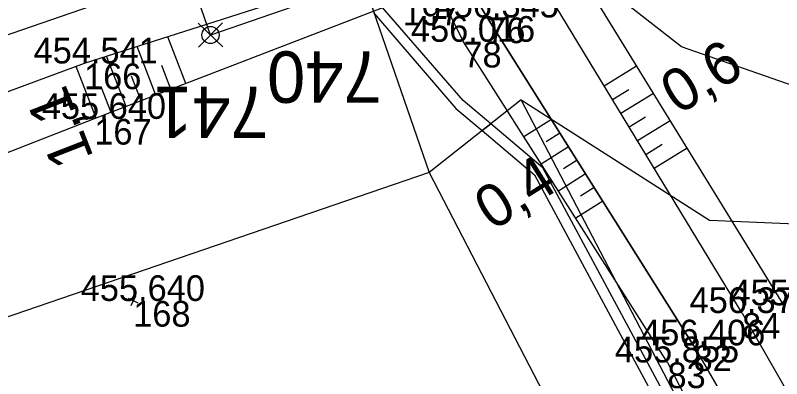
# Model space of a CAD drawing. Extents: x -776734 to -748832, y -1118122 to -976986.
# Drawn here: x -750922.61 to -750886.83, y -1114636.27 to -1114619.29 of the extents above; entities that cross this region are included whole.
import ezdxf

# ---------------------------------------------------------------- set-up
doc = ezdxf.new("R2010")
doc.units = 0
for name, color, linetype in [('KM_Hranice parcel', 7, 'Continuous'), ('KM_Věcná břemena k části', 7, 'Continuous'), ('Obvod stavby - SŽ+ČD', 7, 'Continuous'), ('SŽG Vrstva 48', 7, 'Continuous'), ('SŽG Vrstva 49', 7, 'Continuous'), ('SŽG Vrstva 51', 7, 'Continuous'), ('SŽG Vrstva 53', 7, 'Continuous'), ('SŽG Vrstva 60', 7, 'Continuous'), ('SŽG Vrstva 61', 7, 'Continuous'), ('VYT-BODY', 7, 'Continuous')]:
    doc.layers.add(name, color=color, linetype=linetype)

msp = doc.modelspace()

# ---------------------------------------------------------------- linework, layer by layer
at = {"layer": 'KM_Hranice parcel'}
msp.add_line((-750898.99, -1114623.24), (-750903.28, -1114626.63), dxfattribs=at)
for points in [[(-750899.97, -1114614.15), (-750906.35, -1114617.75), (-750903.28, -1114626.63)], [(-750898.99, -1114623.24), (-750890.19, -1114628.86), (-750790.97, -1114633.08), (-750787.69, -1114636.32), (-750785.63, -1114639.42), (-750784.78, -1114643.94), (-750782.09, -1114625.64), (-750786.55, -1114630.1), (-750878.13, -1114625.43), (-750891.51, -1114620.76), (-750899.97, -1114614.15)], [(-750670.16, -1114976.1), (-750672.09, -1114956.8), (-750700.84, -1114952.52), (-750709.51, -1114952.05), (-750748.78, -1114936.22), (-750768.56, -1114928.51), (-750782.18, -1114919.09), (-750798.79, -1114874.71), (-750803.56, -1114853.05), (-750810, -1114798.7), (-750817.87, -1114778.74), (-750898.99, -1114623.24)], [(-750903.28, -1114626.63), (-750977.55, -1114652.09), (-751017.8, -1114665.47), (-751047.63, -1114693.52)], [(-750903.28, -1114626.63), (-750826.19, -1114775.52), (-750817.2, -1114796.72), (-750809.54, -1114845.73), (-750803.72, -1114890), (-750794.3, -1114916.76)]]:
    msp.add_lwpolyline(points, dxfattribs=at)
at = {"layer": 'KM_Věcná břemena k části'}
msp.add_lwpolyline([(-750902.04, -1114623.64), (-750900.81, -1114624.68), (-750900.41, -1114624.36), (-750901.69, -1114623.28), (-750906.28, -1114617.96), (-750905.84, -1114619.22)], close=True, dxfattribs=at)
msp.add_lwpolyline([(-750864.07, -1114688.15), (-750867.37, -1114681.99), (-750869.16, -1114678.88), (-750873.3, -1114672.49), (-750878.91, -1114662.72), (-750880.52, -1114659.87), (-750884.7, -1114651.27), (-750887.27, -1114646.41), (-750887.94, -1114645.1), (-750897.97, -1114626.42), (-750900.41, -1114624.36), (-750900.81, -1114624.68), (-750898.37, -1114626.74), (-750888.38, -1114645.33), (-750887.67, -1114646.72), (-750885.15, -1114651.49), (-750880.97, -1114660.09), (-750879.19, -1114663.23), (-750873.73, -1114672.72), (-750870.82, -1114677.24), (-750869.61, -1114679.12), (-750867.78, -1114682.28), (-750864.58, -1114688.26)], dxfattribs=at)
at = {"layer": 'Obvod stavby - SŽ+ČD'}
msp.add_lwpolyline([(-751001.9301, -1114630.5149), (-750919.7259, -1114602.1536), (-750923.65, -1114590.78), (-750909.46, -1114590.94), (-750904.52, -1114591.74), (-750900.07, -1114579.45), (-750884.93, -1114572.87), (-750860.41, -1114581.47), (-750855.8233, -1114579.7245), (-750849.5295, -1114597.9668), (-750894.76, -1114611.21), (-750899.97, -1114614.15), (-750906.35, -1114617.75), (-750913.4946, -1114620.2148), (-750914.5076, -1114617.2787), (-750996.7117, -1114645.64)], dxfattribs=at)
at = {"layer": 'SŽG Vrstva 48'}
for p, q in [((-750914.639, -1114622.476), (-750915.483, -1114620.292)), ((-750916.038, -1114623.017), (-750916.914, -1114620.75)), ((-750917.437, -1114623.558), (-750918.346, -1114621.208)), ((-750918.836, -1114624.099), (-750919.77, -1114621.682)), ((-750915.338, -1114622.746), (-750915.768, -1114621.634)), ((-750895.1187, -1114622.5838), (-750893.5969, -1114621.6484)), ((-750916.737, -1114623.287), (-750917.184, -1114622.133)), ((-750918.136, -1114623.828), (-750918.599, -1114622.633)), ((-750894.7294, -1114623.2249), (-750893.9668, -1114622.7561)), ((-750894.3401, -1114623.866), (-750892.8114, -1114622.9263)), ((-750897.5759, -1114624.1615), (-750898.8571, -1114624.9765)), ((-750893.9509, -1114624.5071), (-750893.1848, -1114624.0361)), ((-750893.5616, -1114625.1482), (-750892.0259, -1114624.2042)), ((-750897.1765, -1114624.7963), (-750897.8155, -1114625.2028)), ((-750896.7771, -1114625.4311), (-750898.052, -1114626.2421)), ((-750893.1724, -1114625.7892), (-750892.4027, -1114625.3162)), ((-750892.7831, -1114626.4303), (-750891.2404, -1114625.4821)), ((-750896.3777, -1114626.0659), (-750897.0136, -1114626.4704)), ((-750895.9783, -1114626.7007), (-750897.2469, -1114627.5077)), ((-750895.5789, -1114627.3355), (-750896.2116, -1114627.738)), ((-750895.1794, -1114627.9703), (-750896.4418, -1114628.7733))]:
    msp.add_line(p, q, dxfattribs=at)
at = {"layer": 'SŽG Vrstva 49'}
for p, q in [((-750886.717, -1114632.841), (-750896.148, -1114617.498)), ((-750888.672, -1114633.201), (-750897.925, -1114617.962)), ((-750916.8773, -1114632.7476), (-750917.3267, -1114632.5284)), ((-750916.9924, -1114632.4133), (-750917.2116, -1114632.8627)), ((-750888.672, -1114633.201), (-750881.58, -1114645.562)), ((-750890.937, -1114634.713), (-750885.684, -1114643.833)), ((-750892.157, -1114635.509), (-750887.082, -1114645.369))]:
    msp.add_line(p, q, dxfattribs=at)
for points in [[(-750892.157, -1114635.509), (-750901.685, -1114620.531), (-750905.65, -1114612.465), (-750907.049, -1114607.083)], [(-750890.937, -1114634.713), (-750900.575, -1114619.395), (-750904.321, -1114613.107), (-750907.049, -1114607.083)], [(-750906.794, -1114617.513), (-750919.397, -1114621.544), (-750967.828, -1114639.504)], [(-750904.524, -1114618.563), (-750918.921, -1114624.132), (-750966.612, -1114642.791)]]:
    msp.add_lwpolyline(points, dxfattribs=at)
at = {"layer": 'SŽG Vrstva 51'}
msp.add_line((-750888.672, -1114633.201), (-750897.925, -1114617.962), dxfattribs=at)
msp.add_lwpolyline([(-750907.049, -1114607.083), (-750904.321, -1114613.107), (-750900.575, -1114619.395), (-750890.937, -1114634.713)], dxfattribs=at)
at = {"layer": 'SŽG Vrstva 53'}
msp.add_lwpolyline([(-750804.97, -1114584.92), (-750894.76, -1114611.21), (-750899.97, -1114614.15), (-750906.35, -1114617.75), (-750903.28, -1114626.63), (-750977.55, -1114652.09), (-751017.8, -1114665.47), (-751047.63, -1114693.52)], dxfattribs=at)
at = {"layer": 'SŽG Vrstva 60'}
for p, q in [((-750900.575, -1114619.395), (-750900.575, -1114619.395)), ((-750901.685, -1114620.531), (-750901.685, -1114620.531)), ((-750919.397, -1114621.544), (-750919.397, -1114621.544)), ((-750918.921, -1114624.132), (-750918.921, -1114624.132)), ((-750917.102, -1114632.638), (-750917.102, -1114632.638)), ((-750888.672, -1114633.201), (-750888.672, -1114633.201)), ((-750890.937, -1114634.713), (-750890.937, -1114634.713)), ((-750892.157, -1114635.509), (-750892.157, -1114635.509))]:
    msp.add_line(p, q, dxfattribs=at)
at = {"layer": 'VYT-BODY'}
for p, q in [((-750914.0672, -1114619.6571), (-750912.92, -1114620.7724)), ((-750912.936, -1114619.6411), (-750914.0512, -1114620.7884))]:
    msp.add_line(p, q, dxfattribs=at)
msp.add_circle((-750913.4936, -1114620.2148), 0.4, dxfattribs=at)

# ---------------------------------------------------------------- texts
at = {"layer": 'Obvod stavby - SŽ+ČD'}
for s, p in [('740', (-750905.5, -1114620.9797)), ('741', (-750910.7769, -1114622.6241))]:
    msp.add_text(s, height=2.4, rotation=180, dxfattribs=at).set_placement(p)
at = {"layer": 'SŽG Vrstva 48'}
for s, rotation, p in [('0,6', 31.57812, (-750891.6545, -1114623.9701)), ('1,1', 111.36781, (-750918.9333, -1114625.9313)), ('0,4', 32.17787, (-750900.3315, -1114629.3904))]:
    msp.add_text(s, height=2, rotation=rotation, dxfattribs=at).set_placement(p)
at = {"layer": 'SŽG Vrstva 60'}
for s, p in [('197', (-750904.524, -1114619.763)), ('76', (-750900.575, -1114620.595)), ('78', (-750901.685, -1114621.731)), ('166', (-750919.397, -1114622.744)), ('167', (-750918.921, -1114625.332)), ('168', (-750917.102, -1114633.838)), ('84', (-750888.672, -1114634.401)), ('82', (-750890.937, -1114635.913)), ('83', (-750892.157, -1114636.709))]:
    msp.add_text(s, height=1.2, dxfattribs=at).set_placement(p)
at = {"layer": 'SŽG Vrstva 61'}
for s, p in [('456.345', (-750903.0311, -1114619.395)), ('456.016', (-750904.1369, -1114620.531)), ('454.541', (-750921.7544, -1114621.544)), ('455.640', (-750921.372, -1114624.132)), ('455.640', (-750919.553, -1114632.638)), ('455.716', (-750889.1689, -1114632.841)), ('456.379', (-750891.1257, -1114633.201)), ('456.406', (-750893.3889, -1114634.713)), ('455.855', (-750894.6131, -1114635.509))]:
    msp.add_text(s, height=1.2, dxfattribs=at).set_placement(p)

doc.saveas('drawing.dxf')
